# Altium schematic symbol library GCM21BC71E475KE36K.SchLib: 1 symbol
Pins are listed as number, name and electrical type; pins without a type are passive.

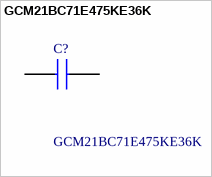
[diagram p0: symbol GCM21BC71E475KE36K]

## GCM21BC71E475KE36K
designator C?
Capacitor GCM21 L=2.0mm W=1.25mm T=1.25mm; Manufacturer_Name: Murata Electronics; Geometry.Height: 1.4mm
footprint CAPC2012X140N
pins: 1, 2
